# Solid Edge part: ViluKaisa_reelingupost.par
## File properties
Author: kaisa
Template: iso metric part.par
Last saved by: kaisa
Revision: 13
Application: Solid Edge
Accuracy: 0.990
Username: kaisa
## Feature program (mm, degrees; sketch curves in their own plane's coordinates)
sketch for "unnamed Protrusion 1" plane through (0, 0, 0) normal (0, 0, 1) x-axis (1, 0, 0)
  circle centre (0, 0) radius 1
extrude "unnamed Protrusion 1" add finite 15 along +normal
sketch for "ExtrudedProtrusion_2" plane through (0, 0, 0) normal (1, 0, 0) x-axis (0, 1, 0)
  circle centre (0, 15) radius 2
extrude "ExtrudedProtrusion_2" add finite 3 symmetric
sketch for "ExtrudedCutout_2" plane through (-1.5, 0, 15) normal (-1, 0, 0) x-axis (0, -1, 0)
extrude "ExtrudedCutout_2" cut finite 5 along -normal
fillet "Round_5" radius 0.3
fillet "Round_6" radius 0.39
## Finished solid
Body 1: solid body, 9 faces, 9 edges, 0 vertices.
  Faces by surface: cylinder 3, plane 3, torus 2, blend 1
  Edges by curve: circle 7, intersection 2
Bounding box of the edges (mm; curved faces can reach further): 3.000 x 4.000 x 17.000, from (-1.5, -2, 0) to (1.5, 2, 17).
Cylindrical faces by radius (mm): R1 x1, R1.5 x1, R2 x1
Toroidal faces (ring radius, tube radius in mm): R1.8 r0.3 x2
Planar faces by outward normal: +x 1, -x 1, -z 1
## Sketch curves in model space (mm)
circle centre (0, 0, 15) radius 2
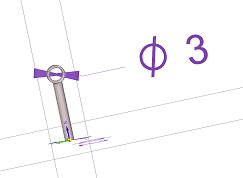
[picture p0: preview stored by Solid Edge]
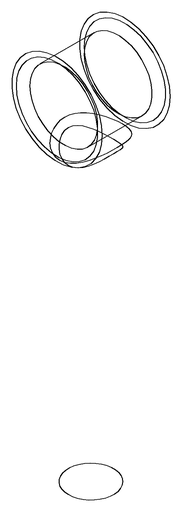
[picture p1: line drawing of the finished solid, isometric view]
